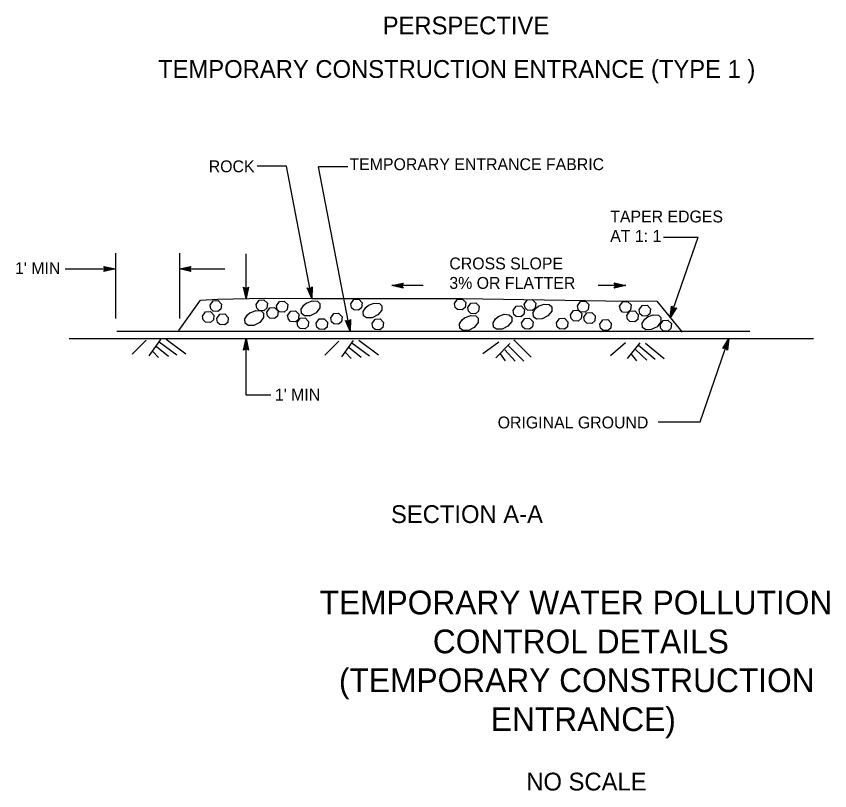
# Model space of a CAD drawing. Extents: x 6709491 to 6710959, y 1869789 to 1870763.
# Drawn here: x 6710441 to 6710852.6, y 1869804.3 to 1870196.2 of the extents above; entities that cross this region are included whole.
import ezdxf

# ---------------------------------------------------------------- set-up
doc = ezdxf.new("R2010")
doc.units = 0
for name, color, linetype in [('10 Sheet Formats', 7, 'Continuous'), ('56 Stg 3 Anno', 7, 'Continuous'), ('57 Undefined', 7, 'Continuous'), ('59 Soundwall Ann', 7, 'Continuous'), ('60 Nongeo Data', 7, 'Continuous')]:
    doc.layers.add(name, color=color, linetype=linetype)

msp = doc.modelspace()

# ---------------------------------------------------------------- linework, layer by layer
at = {"layer": '56 Stg 3 Anno'}
for p, q in [((6710577.77, 1870120.29), (6710562.94, 1870120.29)), ((6710590.62, 1870053.41), (6710577.77, 1870120.29)), ((6710609.91, 1870036.94), (6710593.95, 1870120.03)), ((6710608.78, 1870120.03), (6710593.95, 1870120.03)), ((6710768.54, 1870084.46), (6710786.08, 1870084.46)), ((6710771.94, 1870043.7), (6710786.08, 1870084.46)), ((6710491.13, 1870076.42), (6710491.13, 1870043.28)), ((6710523.55, 1870076.42), (6710523.55, 1870043.28)), ((6710557.31, 1870053.34), (6710557.31, 1870076.04)), ((6710486.14, 1870068.37), (6710485.37, 1870069.66)), ((6710485.37, 1870069.66), (6710485.37, 1870069.66)), ((6710485.37, 1870069.66), (6710491.13, 1870068.37)), ((6710523.55, 1870068.37), (6710529.31, 1870069.65)), ((6710529.31, 1870069.65), (6710528.54, 1870068.37)), ((6710529.31, 1870069.65), (6710529.31, 1870069.65)), ((6710465.81, 1870068.37), (6710491.13, 1870068.37)), ((6710491.13, 1870068.37), (6710485.37, 1870067.09)), ((6710485.37, 1870067.09), (6710486.14, 1870068.37)), ((6710485.37, 1870067.09), (6710485.37, 1870067.09)), ((6710485.58, 1870069.31), (6710489.8, 1870068.37)), ((6710489.79, 1870068.37), (6710485.59, 1870067.44)), ((6710488.48, 1870068.37), (6710485.76, 1870067.77)), ((6710485.8, 1870068.97), (6710488.48, 1870068.37)), ((6710485.97, 1870068.64), (6710487.15, 1870068.37)), ((6710487.15, 1870068.37), (6710485.99, 1870068.12)), ((6710491.13, 1870068.37), (6710491.13, 1870068.37)), ((6710523.55, 1870068.37), (6710546.59, 1870068.37)), ((6710529.31, 1870067.08), (6710523.55, 1870068.37)), ((6710523.55, 1870068.37), (6710523.55, 1870068.37)), ((6710529.1, 1870067.42), (6710524.87, 1870068.37)), ((6710524.88, 1870068.37), (6710529.08, 1870069.3)), ((6710526.2, 1870068.37), (6710528.91, 1870068.97)), ((6710528.88, 1870067.77), (6710526.2, 1870068.37)), ((6710527.53, 1870068.37), (6710528.69, 1870068.62)), ((6710528.71, 1870068.1), (6710527.53, 1870068.37)), ((6710528.54, 1870068.37), (6710529.31, 1870067.08)), ((6710529.31, 1870067.08), (6710529.31, 1870067.08)), ((6710631.02, 1870059.97), (6710636.78, 1870061.24)), ((6710636.78, 1870061.24), (6710636.01, 1870059.97)), ((6710636.78, 1870061.24), (6710636.78, 1870061.24)), ((6710744.4, 1870059.97), (6710743.63, 1870061.25)), ((6710743.63, 1870061.25), (6710743.63, 1870061.25)), ((6710743.63, 1870061.25), (6710749.39, 1870059.97)), ((6710557.31, 1870053.34), (6710556.03, 1870059.1)), ((6710556.03, 1870059.1), (6710556.03, 1870059.1)), ((6710556.03, 1870059.1), (6710557.31, 1870058.33)), ((6710557.31, 1870054.68), (6710556.38, 1870058.87)), ((6710557.31, 1870055.99), (6710556.71, 1870058.7)), ((6710557.31, 1870057.32), (6710557.06, 1870058.48)), ((6710557.31, 1870058.33), (6710558.6, 1870059.1)), ((6710558.6, 1870059.1), (6710557.31, 1870053.34)), ((6710558.26, 1870058.89), (6710557.31, 1870054.66)), ((6710557.91, 1870058.67), (6710557.31, 1870055.99)), ((6710557.58, 1870058.5), (6710557.31, 1870057.32)), ((6710558.6, 1870059.1), (6710558.6, 1870059.1)), ((6710590.62, 1870053.41), (6710588.28, 1870058.82)), ((6710588.28, 1870058.82), (6710588.28, 1870058.82)), ((6710588.28, 1870058.82), (6710589.68, 1870058.31)), ((6710590.37, 1870054.72), (6710588.66, 1870058.67)), ((6710590.12, 1870056.01), (6710589.02, 1870058.56)), ((6710589.87, 1870057.31), (6710589.4, 1870058.41)), ((6710589.68, 1870058.31), (6710590.8, 1870059.31)), ((6710589.91, 1870058.52), (6710589.87, 1870057.31)), ((6710590.21, 1870058.75), (6710590.12, 1870056.01)), ((6710590.5, 1870059.04), (6710590.37, 1870054.71)), ((6710590.8, 1870059.31), (6710590.62, 1870053.41)), ((6710590.8, 1870059.31), (6710590.8, 1870059.31)), ((6710646.98, 1870059.97), (6710631.02, 1870059.97)), ((6710636.78, 1870058.68), (6710631.02, 1870059.97)), ((6710631.02, 1870059.97), (6710631.02, 1870059.97)), ((6710636.57, 1870059.02), (6710632.34, 1870059.97)), ((6710632.35, 1870059.97), (6710636.55, 1870060.9)), ((6710633.67, 1870059.96), (6710636.38, 1870060.57)), ((6710636.34, 1870059.37), (6710633.67, 1870059.96)), ((6710634.99, 1870059.96), (6710636.15, 1870060.22)), ((6710636.17, 1870059.7), (6710634.99, 1870059.96)), ((6710636.01, 1870059.97), (6710636.78, 1870058.68)), ((6710636.78, 1870058.68), (6710636.78, 1870058.68)), ((6710749.39, 1870059.97), (6710735.38, 1870059.97)), ((6710749.39, 1870059.97), (6710743.63, 1870058.69)), ((6710743.63, 1870058.69), (6710744.4, 1870059.97)), ((6710743.63, 1870058.69), (6710743.63, 1870058.69)), ((6710743.84, 1870060.91), (6710748.07, 1870059.97)), ((6710748.06, 1870059.96), (6710743.86, 1870059.03)), ((6710746.74, 1870059.97), (6710744.03, 1870059.37)), ((6710744.07, 1870060.57), (6710746.74, 1870059.97)), ((6710744.24, 1870060.23), (6710745.42, 1870059.97)), ((6710745.42, 1870059.97), (6710744.26, 1870059.71)), ((6710749.39, 1870059.97), (6710749.39, 1870059.97)), ((6710557.31, 1870053.34), (6710557.31, 1870053.34)), ((6710590.62, 1870053.41), (6710590.62, 1870053.41)), ((6710771.94, 1870043.7), (6710772.62, 1870049.56)), ((6710772.37, 1870044.96), (6710772.87, 1870049.23)), ((6710772.62, 1870049.56), (6710772.62, 1870049.56)), ((6710772.62, 1870049.56), (6710773.58, 1870048.41)), ((6710772.81, 1870046.2), (6710773.13, 1870048.96)), ((6710775.04, 1870048.72), (6710771.94, 1870043.7)), ((6710774.65, 1870048.63), (6710772.37, 1870044.95)), ((6710774.25, 1870048.53), (6710772.81, 1870046.2)), ((6710773.25, 1870047.45), (6710773.38, 1870048.63)), ((6710773.88, 1870048.48), (6710773.25, 1870047.45)), ((6710773.58, 1870048.41), (6710775.04, 1870048.72)), ((6710775.04, 1870048.72), (6710775.04, 1870048.72)), ((6710609.91, 1870036.94), (6710607.57, 1870042.35)), ((6710607.57, 1870042.35), (6710607.57, 1870042.35)), ((6710607.57, 1870042.35), (6710608.97, 1870041.84)), ((6710609.66, 1870038.25), (6710607.96, 1870042.2)), ((6710609.42, 1870039.54), (6710608.31, 1870042.09)), ((6710609.17, 1870040.84), (6710608.7, 1870041.93)), ((6710608.97, 1870041.84), (6710610.09, 1870042.84)), ((6710609.2, 1870042.05), (6710609.17, 1870040.84)), ((6710609.5, 1870042.28), (6710609.42, 1870039.54)), ((6710609.8, 1870042.57), (6710609.67, 1870038.24)), ((6710610.09, 1870042.84), (6710609.91, 1870036.94)), ((6710610.09, 1870042.84), (6710610.09, 1870042.84)), ((6710771.94, 1870043.7), (6710771.94, 1870043.7)), ((6710609.91, 1870036.94), (6710609.91, 1870036.94)), ((6710556.03, 1870027.33), (6710557.31, 1870033.09)), ((6710557.31, 1870004.56), (6710557.31, 1870033.09)), ((6710557.31, 1870033.09), (6710557.31, 1870033.09)), ((6710557.31, 1870033.09), (6710558.59, 1870027.33)), ((6710787.05, 1869990.95), (6710801.67, 1870033.11)), ((6710798.57, 1870028.09), (6710801.67, 1870033.11)), ((6710801.67, 1870033.11), (6710800.99, 1870027.25)), ((6710801.67, 1870033.11), (6710801.67, 1870033.11)), ((6710556.37, 1870027.54), (6710557.31, 1870031.77)), ((6710556.71, 1870027.77), (6710557.31, 1870030.44)), ((6710557.04, 1870027.93), (6710557.31, 1870029.11)), ((6710557.31, 1870031.76), (6710558.24, 1870027.56)), ((6710557.31, 1870030.44), (6710557.91, 1870027.73)), ((6710557.31, 1870029.11), (6710557.57, 1870027.95)), ((6710800.04, 1870028.39), (6710798.57, 1870028.09)), ((6710798.96, 1870028.17), (6710801.24, 1870031.86)), ((6710799.36, 1870028.27), (6710800.8, 1870030.6)), ((6710799.73, 1870028.32), (6710800.37, 1870029.35)), ((6710800.99, 1870027.25), (6710800.04, 1870028.39)), ((6710800.37, 1870029.35), (6710800.23, 1870028.17)), ((6710800.8, 1870030.6), (6710800.48, 1870027.84)), ((6710801.24, 1870031.84), (6710800.74, 1870027.57)), ((6710557.31, 1870028.1), (6710556.03, 1870027.33)), ((6710556.03, 1870027.33), (6710556.03, 1870027.33)), ((6710558.59, 1870027.33), (6710557.31, 1870028.1)), ((6710558.59, 1870027.33), (6710558.59, 1870027.33)), ((6710798.57, 1870028.09), (6710798.57, 1870028.09)), ((6710800.99, 1870027.25), (6710800.99, 1870027.25)), ((6710569.84, 1870004.56), (6710557.31, 1870004.56)), ((6710765.86, 1869990.95), (6710787.05, 1869990.95))]:
    msp.add_line(p, q, dxfattribs=at)
at = {"layer": '59 Soundwall Ann'}
for p, q in [((6710506.78, 1870032.33), (6710499.61, 1870025.22)), ((6710513.93, 1870032.67), (6710508.15, 1870024.43)), ((6710516.84, 1870032.8), (6710526.79, 1870025.47)), ((6710692.73, 1870032.48), (6710701.51, 1870023.78)), ((6710511.95, 1870029.19), (6710518.05, 1870024.21)), ((6710513.39, 1870031.45), (6710522.28, 1870024.9)), ((6710604.29, 1870031.82), (6710597.12, 1870024.7)), ((6710611.44, 1870032.16), (6710605.66, 1870023.91)), ((6710609.45, 1870028.67), (6710615.56, 1870023.69)), ((6710610.89, 1870030.94), (6710619.79, 1870024.39)), ((6710614.34, 1870032.28), (6710624.3, 1870024.96)), ((6710685.24, 1870031.37), (6710677.11, 1870025.37)), ((6710690.68, 1870030.67), (6710683.76, 1870023.35)), ((6710689.96, 1870029.54), (6710697.81, 1870021.77)), ((6710749.31, 1870031), (6710741.73, 1870024.33)), ((6710756.47, 1870030.92), (6710750.21, 1870023.03)), ((6710755.85, 1870029.73), (6710764.34, 1870022.66)), ((6710759.38, 1870030.87), (6710768.87, 1870022.96)), ((6710510.01, 1870026.8), (6710512.91, 1870023.61)), ((6710607.51, 1870026.29), (6710610.42, 1870023.09)), ((6710685.94, 1870025.43), (6710688.35, 1870021.85)), ((6710688.21, 1870027.51), (6710693.52, 1870021.7)), ((6710752.2, 1870025.29), (6710754.91, 1870021.93)), ((6710754.28, 1870027.55), (6710760.08, 1870022.22))]:
    msp.add_line(p, q, dxfattribs=at)
at = {"layer": '60 Nongeo Data'}
for p, q in [((6710491.88, 1870036.94), (6710638.48, 1870036.94)), ((6710638.48, 1870036.94), (6710812.22, 1870036.94)), ((6710467.82, 1870033.11), (6710637.9, 1870033.11)), ((6710637.9, 1870033.11), (6710844.47, 1870033.11))]:
    msp.add_line(p, q, dxfattribs=at)
for points in [[(6710523.29, 1870037.15), (6710534.22, 1870052.61), (6710543, 1870053.06), (6710566.73, 1870053.52), (6710590.57, 1870053.41), (6710641.46, 1870053.45)], [(6710610.27, 1870050.67), (6710611.82, 1870052.87), (6710614.3, 1870053.01), (6710616.02, 1870051.23), (6710615.77, 1870048.73), (6710614.24, 1870047.46), (6710611.8, 1870047.64), (6710610.65, 1870048.75), (6710610.27, 1870050.67)], [(6710641.46, 1870053.45), (6710666.79, 1870053.47), (6710739.37, 1870052.21), (6710765.14, 1870052.09), (6710777.89, 1870036.35)], [(6710662.71, 1870050.8), (6710664.26, 1870053), (6710666.73, 1870053.15), (6710668.45, 1870051.36), (6710668.2, 1870048.86), (6710666.68, 1870047.59), (6710664.23, 1870047.77), (6710663.08, 1870048.88), (6710662.71, 1870050.8)], [(6710698.1, 1870050.55), (6710699.65, 1870052.75), (6710702.12, 1870052.89), (6710703.84, 1870051.11), (6710703.59, 1870048.61), (6710702.07, 1870047.34), (6710699.62, 1870047.51), (6710698.47, 1870048.63), (6710698.1, 1870050.55)], [(6710539.06, 1870050.02), (6710540.61, 1870052.23), (6710543.09, 1870052.37), (6710544.8, 1870050.59), (6710544.56, 1870048.08), (6710543.03, 1870046.81), (6710540.58, 1870046.99), (6710539.43, 1870048.11), (6710539.06, 1870050.02)], [(6710562.32, 1870050.4), (6710563.87, 1870052.6), (6710566.34, 1870052.74), (6710568.06, 1870050.96), (6710567.81, 1870048.46), (6710566.28, 1870047.19), (6710563.84, 1870047.37), (6710562.69, 1870048.48), (6710562.32, 1870050.4)], [(6710567.72, 1870046.47), (6710569.27, 1870048.67), (6710571.75, 1870048.81), (6710573.47, 1870047.03), (6710573.22, 1870044.53), (6710571.69, 1870043.26), (6710569.25, 1870043.44), (6710568.1, 1870044.55), (6710567.73, 1870046.47)], [(6710572.61, 1870049.73), (6710574.16, 1870051.94), (6710576.64, 1870052.08), (6710578.36, 1870050.29), (6710578.11, 1870047.79), (6710576.58, 1870046.52), (6710574.14, 1870046.7), (6710572.99, 1870047.81), (6710572.62, 1870049.73)], [(6710587.83, 1870051.08), (6710590.73, 1870052.23), (6710593.4, 1870052), (6710594.66, 1870050.8), (6710594.62, 1870048.63), (6710592.7, 1870046.18), (6710589.73, 1870044.69), (6710586.93, 1870044.64), (6710585.36, 1870045.76), (6710585.21, 1870047.99), (6710586.48, 1870049.99), (6710587.95, 1870051.15)], [(6710619.17, 1870049.97), (6710622.07, 1870051.12), (6710624.74, 1870050.89), (6710626, 1870049.69), (6710625.96, 1870047.53), (6710624.04, 1870045.07), (6710621.07, 1870043.59), (6710618.27, 1870043.54), (6710616.7, 1870044.66), (6710616.55, 1870046.89), (6710617.83, 1870048.88), (6710619.29, 1870050.05)], [(6710669.5, 1870048.89), (6710671.05, 1870051.09), (6710673.52, 1870051.23), (6710675.24, 1870049.45), (6710674.99, 1870046.95), (6710673.46, 1870045.68), (6710671.02, 1870045.86), (6710669.87, 1870046.97), (6710669.5, 1870048.89)], [(6710692.39, 1870047.28), (6710693.94, 1870049.49), (6710696.42, 1870049.63), (6710698.14, 1870047.85), (6710697.89, 1870045.35), (6710696.36, 1870044.07), (6710693.92, 1870044.25), (6710692.77, 1870045.37), (6710692.4, 1870047.28)], [(6710705.17, 1870049.45), (6710708.07, 1870050.6), (6710710.73, 1870050.37), (6710712, 1870049.16), (6710711.96, 1870047), (6710710.03, 1870044.55), (6710707.06, 1870043.06), (6710704.27, 1870043.01), (6710702.69, 1870044.13), (6710702.54, 1870046.36), (6710703.82, 1870048.36), (6710705.28, 1870049.52)], [(6710724.99, 1870049.73), (6710726.54, 1870051.94), (6710729.01, 1870052.08), (6710730.73, 1870050.29), (6710730.48, 1870047.79), (6710728.95, 1870046.52), (6710726.51, 1870046.7), (6710725.36, 1870047.81), (6710724.99, 1870049.73)], [(6710746.34, 1870049.58), (6710747.89, 1870051.78), (6710750.36, 1870051.92), (6710752.08, 1870050.14), (6710751.84, 1870047.64), (6710750.31, 1870046.37), (6710747.86, 1870046.54), (6710746.71, 1870047.66), (6710746.34, 1870049.57)], [(6710756.18, 1870047.62), (6710757.73, 1870049.82), (6710760.2, 1870049.96), (6710761.92, 1870048.18), (6710761.67, 1870045.68), (6710760.14, 1870044.41), (6710757.7, 1870044.59), (6710756.55, 1870045.7), (6710756.18, 1870047.62)], [(6710535.28, 1870044.47), (6710536.84, 1870046.67), (6710539.31, 1870046.82), (6710541.03, 1870045.03), (6710540.78, 1870042.53), (6710539.25, 1870041.26), (6710536.81, 1870041.44), (6710535.66, 1870042.55), (6710535.29, 1870044.47)], [(6710542.5, 1870043.25), (6710544.05, 1870045.45), (6710546.53, 1870045.59), (6710548.25, 1870043.81), (6710548, 1870041.31), (6710546.47, 1870040.04), (6710544.02, 1870040.22), (6710542.87, 1870041.33), (6710542.5, 1870043.25)], [(6710559.31, 1870046.19), (6710562.21, 1870047.34), (6710564.88, 1870047.11), (6710566.14, 1870045.9), (6710566.1, 1870043.74), (6710564.18, 1870041.29), (6710561.21, 1870039.8), (6710558.41, 1870039.75), (6710556.84, 1870040.87), (6710556.69, 1870043.1), (6710557.97, 1870045.09), (6710559.43, 1870046.26)], [(6710578.32, 1870044.84), (6710579.87, 1870047.04), (6710582.34, 1870047.18), (6710584.06, 1870045.4), (6710583.81, 1870042.9), (6710582.29, 1870041.63), (6710579.84, 1870041.81), (6710578.69, 1870042.92), (6710578.32, 1870044.84)], [(6710600.11, 1870043.58), (6710601.66, 1870045.79), (6710604.13, 1870045.93), (6710605.85, 1870044.14), (6710605.6, 1870041.64), (6710604.07, 1870040.37), (6710601.63, 1870040.55), (6710600.48, 1870041.66), (6710600.11, 1870043.58)], [(6710667.92, 1870043.68), (6710670.82, 1870044.83), (6710673.48, 1870044.6), (6710674.75, 1870043.4), (6710674.71, 1870041.23), (6710672.78, 1870038.78), (6710669.81, 1870037.29), (6710667.02, 1870037.24), (6710665.44, 1870038.36), (6710665.29, 1870040.59), (6710666.57, 1870042.59), (6710668.03, 1870043.76)], [(6710684.92, 1870044.25), (6710687.82, 1870045.4), (6710690.49, 1870045.17), (6710691.75, 1870043.96), (6710691.71, 1870041.8), (6710689.79, 1870039.35), (6710686.82, 1870037.86), (6710684.02, 1870037.81), (6710682.45, 1870038.93), (6710682.3, 1870041.16), (6710683.58, 1870043.15), (6710685.04, 1870044.32)], [(6710721.39, 1870045.21), (6710722.95, 1870047.41), (6710725.42, 1870047.56), (6710727.14, 1870045.77), (6710726.89, 1870043.27), (6710725.36, 1870042), (6710722.92, 1870042.18), (6710721.77, 1870043.29), (6710721.4, 1870045.21)], [(6710728.25, 1870044.02), (6710729.8, 1870046.23), (6710732.27, 1870046.37), (6710733.99, 1870044.59), (6710733.74, 1870042.08), (6710732.21, 1870040.81), (6710729.77, 1870040.99), (6710728.62, 1870042.1), (6710728.25, 1870044.02)], [(6710750, 1870044.8), (6710751.55, 1870047), (6710754.03, 1870047.15), (6710755.75, 1870045.36), (6710755.5, 1870042.86), (6710753.97, 1870041.59), (6710751.53, 1870041.77), (6710750.38, 1870042.88), (6710750, 1870044.8)], [(6710760.42, 1870044.05), (6710763.32, 1870045.2), (6710765.98, 1870044.97), (6710767.25, 1870043.76), (6710767.21, 1870041.6), (6710765.29, 1870039.15), (6710762.32, 1870037.66), (6710759.52, 1870037.61), (6710757.94, 1870038.73), (6710757.79, 1870040.96), (6710759.07, 1870042.96), (6710760.54, 1870044.12)], [(6710583.17, 1870041.28), (6710584.72, 1870043.48), (6710587.2, 1870043.62), (6710588.92, 1870041.84), (6710588.67, 1870039.34), (6710587.14, 1870038.07), (6710584.7, 1870038.25), (6710583.55, 1870039.36), (6710583.17, 1870041.28)], [(6710592.81, 1870040.85), (6710594.36, 1870043.05), (6710596.84, 1870043.19), (6710598.56, 1870041.41), (6710598.31, 1870038.91), (6710596.78, 1870037.64), (6710594.33, 1870037.81), (6710593.18, 1870038.93), (6710592.81, 1870040.84)], [(6710621.05, 1870040.73), (6710622.6, 1870042.93), (6710625.08, 1870043.07), (6710626.8, 1870041.29), (6710626.55, 1870038.79), (6710625.02, 1870037.52), (6710622.57, 1870037.69), (6710621.43, 1870038.81), (6710621.05, 1870040.72)], [(6710696.75, 1870041.03), (6710698.3, 1870043.24), (6710700.78, 1870043.38), (6710702.5, 1870041.59), (6710702.25, 1870039.09), (6710700.72, 1870037.82), (6710698.28, 1870038), (6710697.13, 1870039.12), (6710696.75, 1870041.03)], [(6710714.39, 1870041.06), (6710715.94, 1870043.26), (6710718.42, 1870043.41), (6710720.14, 1870041.62), (6710719.89, 1870039.12), (6710718.36, 1870037.85), (6710715.91, 1870038.03), (6710714.76, 1870039.14), (6710714.39, 1870041.06)], [(6710736.34, 1870040.36), (6710737.89, 1870042.56), (6710740.36, 1870042.71), (6710742.08, 1870040.92), (6710741.83, 1870038.42), (6710740.3, 1870037.15), (6710737.86, 1870037.33), (6710736.71, 1870038.44), (6710736.34, 1870040.36)], [(6710766.76, 1870040.14), (6710768.31, 1870042.34), (6710770.79, 1870042.48), (6710772.51, 1870040.7), (6710772.26, 1870038.2), (6710770.73, 1870036.93), (6710768.29, 1870037.1), (6710767.14, 1870038.22), (6710766.76, 1870040.13)]]:
    msp.add_lwpolyline(points, dxfattribs=at)

# ---------------------------------------------------------------- texts
at = {"layer": '10 Sheet Formats'}
for s, height, p in [('TEMPORARY WATER POLLUTION', 12, (6710594.5, 1869893.56)), ('CONTROL DETAILS', 12, (6710651.8, 1869873.88)), ('(TEMPORARY CONSTRUCTION', 12, (6710604.29, 1869854.2)), ('ENTRANCE)', 12, (6710681.15, 1869834.52)), ('NO SCALE', 9, (6710699.09, 1869804.44))]:
    msp.add_text(s, height=height, dxfattribs=at).set_placement(p)
at = {"layer": '57 Undefined'}
for s, height, p in [('PERSPECTIVE', 9, (6710626.42, 1870187.09)), ('TEMPORARY CONSTRUCTION ENTRANCE (TYPE 1 )', 9, (6710512.77, 1870165.05)), ('ROCK', 6, (6710538.4, 1870117.29)), ('TEMPORARY ENTRANCE FABRIC', 6, (6710609.63, 1870118.36)), ('TAPER EDGES', 6, (6710741.57, 1870091.9)), ('AT 1: 1', 6, (6710741.57, 1870082.07)), ('CROSS SLOPE', 6, (6710660.16, 1870068.13)), ("1' MIN", 6, (6710440.39, 1870065.76)), ('3% OR FLATTER', 6, (6710660.16, 1870058.29)), ("1' MIN", 6, (6710571.88, 1870001.74)), ('ORIGINAL GROUND', 6, (6710684.62, 1869987.67)), ('SECTION A-A', 9, (6710630.62, 1869939.79))]:
    msp.add_text(s, height=height, dxfattribs=at).set_placement(p)

doc.saveas('drawing.dxf')
